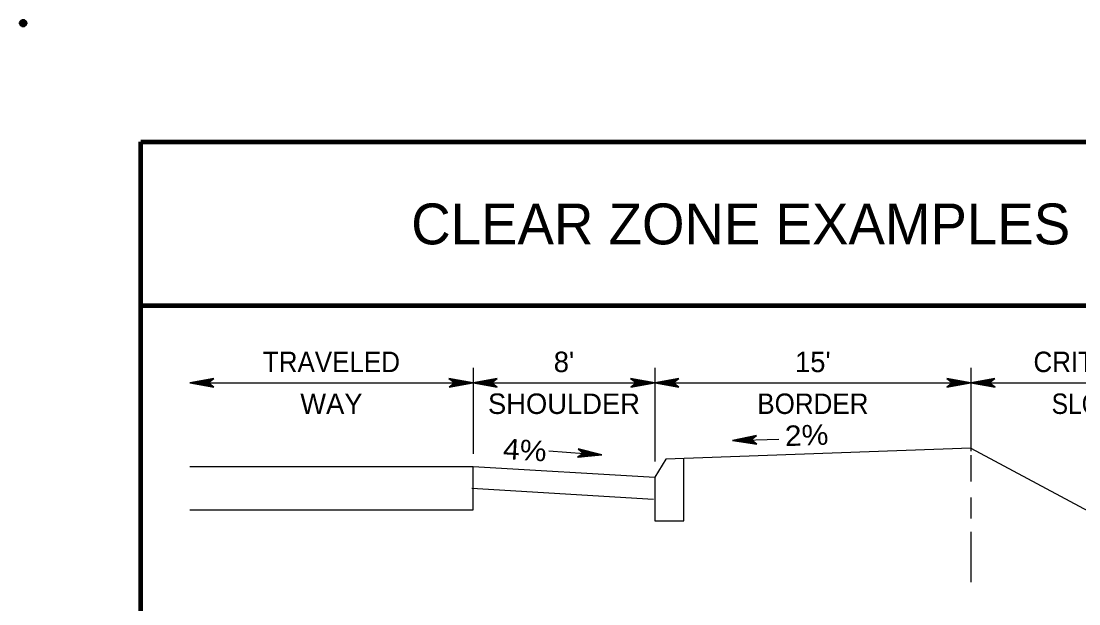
# Model space of a CAD drawing. Extents: x -15.691 to -15.016, y -14.8 to -13.916.
# Drawn here: x -15.6909 to -15.2866, y -14.1387 to -13.9159 of the extents above; entities that cross this region are included whole.
import ezdxf
from ezdxf.enums import TextEntityAlignment as Align

# ---------------------------------------------------------------- set-up
doc = ezdxf.new("R2010")
doc.units = 0
doc.header["$LTSCALE"] = 0.0031
doc.header["$PDMODE"] = 32
doc.header["$PDSIZE"] = 0.00155
for name, color, linetype, lineweight in [('1', 7, 'Continuous', 90), ('24', 7, 'Continuous', 25), ('5', 7, 'Continuous', 25)]:
    doc.layers.add(name, color=color, linetype=linetype, lineweight=lineweight)

msp = doc.modelspace()

# ---------------------------------------------------------------- linework, layer by layer
at = {"layer": '1'}
for p, q in [((-15.645142, -14.753775), (-15.645142, -13.962108)), ((-15.645142, -14.753775), (-15.645142, -13.962108)), ((-15.645142, -14.024608), (-15.061808, -14.024608))]:
    msp.add_line(p, q, dxfattribs=at)
msp.add_lwpolyline([(-15.645142, -13.962108), (-15.186808, -13.962108), (-15.061808, -13.962108)], dxfattribs=at)
msp.add_point((-15.690142, -13.916692), dxfattribs=at)
at = {"layer": '24'}
for p, q in [((-15.518158, -14.048383), (-15.518158, -14.081275)), ((-15.448717, -14.048383), (-15.448717, -14.084308)), ((-15.448717, -14.054167), (-15.327883, -14.054167)), ((-15.327883, -14.054167), (-15.234825, -14.054167)), ((-15.418958, -14.076208), (-15.40125, -14.075708)), ((-15.489158, -14.080208), (-15.468925, -14.081708))]:
    msp.add_line(p, q, dxfattribs=at)
for points in [[(-15.626492, -14.054167), (-15.61725, -14.0558), (-15.619458, -14.054167), (-15.6173, -14.052558), (-15.626492, -14.054167), (-15.625875, -14.05415), (-15.617508, -14.055675), (-15.619633, -14.05415), (-15.617675, -14.052683), (-15.62555, -14.054117), (-15.625242, -14.054167), (-15.618075, -14.055442), (-15.619683, -14.05415), (-15.618025, -14.052892), (-15.6251, -14.054167), (-15.624792, -14.054117), (-15.618525, -14.05525), (-15.619742, -14.054167), (-15.6185, -14.053042), (-15.6239, -14.054117), (-15.623375, -14.054117), (-15.618992, -14.055017), (-15.619842, -14.054192), (-15.618925, -14.053275), (-15.623283, -14.054167), (-15.622792, -14.054192), (-15.619492, -14.054758), (-15.620125, -14.054117), (-15.619442, -14.053483), (-15.622342, -14.054167), (-15.621875, -14.054217), (-15.619892, -14.054592), (-15.620217, -14.05415), (-15.619675, -14.05365), (-15.621633, -14.054167), (-15.620342, -14.054475), (-15.620525, -14.054117), (-15.619958, -14.053767), (-15.621308, -14.054117), (-15.620458, -14.054333), (-15.620817, -14.05405), (-15.620408, -14.053883), (-15.620817, -14.05415), (-15.6206, -14.054192)], [(-15.518158, -14.054167), (-15.5274, -14.052533), (-15.525192, -14.054167), (-15.52735, -14.055775), (-15.518158, -14.054167), (-15.518775, -14.054183), (-15.527142, -14.05265), (-15.525017, -14.054183), (-15.526975, -14.05565), (-15.5191, -14.054208), (-15.519408, -14.054167), (-15.526583, -14.052892), (-15.524975, -14.054183), (-15.526625, -14.055442), (-15.51955, -14.054167), (-15.519858, -14.054208), (-15.526125, -14.053083), (-15.524908, -14.054167), (-15.52615, -14.055292), (-15.52075, -14.054217), (-15.521275, -14.054208), (-15.525658, -14.053317), (-15.524808, -14.054142), (-15.525725, -14.055058), (-15.521367, -14.054167), (-15.521858, -14.054142), (-15.525158, -14.053575), (-15.524525, -14.054217), (-15.525208, -14.054842), (-15.522317, -14.054167), (-15.522775, -14.054117), (-15.524758, -14.053742), (-15.524433, -14.054183), (-15.524975, -14.054683), (-15.523017, -14.054167), (-15.524308, -14.053858), (-15.524125, -14.054208), (-15.524692, -14.054567), (-15.523342, -14.054217), (-15.524192, -14.054), (-15.523833, -14.054283), (-15.524242, -14.05445), (-15.523842, -14.054183), (-15.52405, -14.054142)], [(-15.518158, -14.054167), (-15.508917, -14.0558), (-15.511125, -14.054167), (-15.508967, -14.052558), (-15.518158, -14.054167), (-15.517542, -14.05415), (-15.509175, -14.055675), (-15.5113, -14.05415), (-15.509342, -14.052683), (-15.517217, -14.054117), (-15.516908, -14.054167), (-15.509742, -14.055442), (-15.51135, -14.05415), (-15.509692, -14.052892), (-15.516767, -14.054167), (-15.516458, -14.054117), (-15.510192, -14.05525), (-15.511408, -14.054167), (-15.510167, -14.053042), (-15.515567, -14.054117), (-15.515042, -14.054117), (-15.510658, -14.055017), (-15.511508, -14.054192), (-15.510592, -14.053275), (-15.51495, -14.054167), (-15.514458, -14.054192), (-15.511158, -14.054758), (-15.511792, -14.054117), (-15.511108, -14.053483), (-15.514008, -14.054167), (-15.513542, -14.054217), (-15.511558, -14.054592), (-15.511883, -14.05415), (-15.511342, -14.05365), (-15.5133, -14.054167), (-15.512008, -14.054475), (-15.512192, -14.054117), (-15.511625, -14.053767), (-15.512975, -14.054117), (-15.512125, -14.054333), (-15.512483, -14.05405), (-15.512075, -14.053883), (-15.512475, -14.05415), (-15.512267, -14.054192)], [(-15.448717, -14.054167), (-15.457958, -14.052533), (-15.45575, -14.054167), (-15.457908, -14.055775), (-15.448717, -14.054167), (-15.449325, -14.054183), (-15.457692, -14.05265), (-15.455575, -14.054183), (-15.457533, -14.05565), (-15.449658, -14.054208), (-15.449967, -14.054167), (-15.457133, -14.052892), (-15.455525, -14.054183), (-15.457183, -14.055442), (-15.450108, -14.054167), (-15.450417, -14.054208), (-15.456683, -14.053083), (-15.455458, -14.054167), (-15.456708, -14.055292), (-15.451308, -14.054217), (-15.451825, -14.054208), (-15.456217, -14.053317), (-15.455358, -14.054142), (-15.456283, -14.055058), (-15.451925, -14.054167), (-15.452417, -14.054142), (-15.455717, -14.053575), (-15.455083, -14.054217), (-15.455767, -14.054842), (-15.452867, -14.054167), (-15.453333, -14.054117), (-15.455317, -14.053742), (-15.454992, -14.054183), (-15.455525, -14.054683), (-15.453575, -14.054167), (-15.454867, -14.053858), (-15.454683, -14.054208), (-15.45525, -14.054567), (-15.4539, -14.054217), (-15.45475, -14.054), (-15.454392, -14.054283), (-15.4548, -14.05445), (-15.454392, -14.054183), (-15.454608, -14.054142)], [(-15.448717, -14.054167), (-15.439475, -14.0558), (-15.441683, -14.054167), (-15.439525, -14.052558), (-15.448717, -14.054167), (-15.4481, -14.05415), (-15.439733, -14.055675), (-15.441858, -14.05415), (-15.439892, -14.052683), (-15.447767, -14.054117), (-15.447458, -14.054167), (-15.440292, -14.055442), (-15.4419, -14.05415), (-15.44025, -14.052892), (-15.447325, -14.054167), (-15.447017, -14.054117), (-15.44075, -14.05525), (-15.441967, -14.054167), (-15.440725, -14.053042), (-15.446125, -14.054117), (-15.4456, -14.054117), (-15.441217, -14.055017), (-15.442067, -14.054192), (-15.44115, -14.053275), (-15.445508, -14.054167), (-15.445017, -14.054192), (-15.441717, -14.054758), (-15.44235, -14.054117), (-15.441658, -14.053483), (-15.444558, -14.054167), (-15.444092, -14.054217), (-15.442117, -14.054592), (-15.442442, -14.05415), (-15.4419, -14.05365), (-15.44385, -14.054167), (-15.442558, -14.054475), (-15.44275, -14.054117), (-15.442183, -14.053767), (-15.443525, -14.054117), (-15.442683, -14.054333), (-15.443033, -14.05405), (-15.442625, -14.053883), (-15.443033, -14.05415), (-15.442825, -14.054192)], [(-15.327883, -14.054167), (-15.337125, -14.052533), (-15.334917, -14.054167), (-15.337075, -14.055775), (-15.327883, -14.054167), (-15.328492, -14.054183), (-15.336867, -14.05265), (-15.334742, -14.054183), (-15.3367, -14.05565), (-15.328825, -14.054208), (-15.329133, -14.054167), (-15.3363, -14.052892), (-15.334692, -14.054183), (-15.33635, -14.055442), (-15.329275, -14.054167), (-15.329583, -14.054208), (-15.33585, -14.053083), (-15.334625, -14.054167), (-15.335875, -14.055292), (-15.330475, -14.054217), (-15.330992, -14.054208), (-15.335383, -14.053317), (-15.334533, -14.054142), (-15.33545, -14.055058), (-15.331092, -14.054167), (-15.331583, -14.054142), (-15.334883, -14.053575), (-15.33425, -14.054217), (-15.334933, -14.054842), (-15.332033, -14.054167), (-15.3325, -14.054117), (-15.334483, -14.053742), (-15.334158, -14.054183), (-15.334692, -14.054683), (-15.332742, -14.054167), (-15.334033, -14.053858), (-15.33385, -14.054208), (-15.334417, -14.054567), (-15.333067, -14.054217), (-15.333917, -14.054), (-15.333558, -14.054283), (-15.333967, -14.05445), (-15.333558, -14.054183), (-15.333775, -14.054142)], [(-15.327883, -14.054167), (-15.318642, -14.0558), (-15.32085, -14.054167), (-15.318692, -14.052558), (-15.327883, -14.054167), (-15.327267, -14.05415), (-15.3189, -14.055675), (-15.321025, -14.05415), (-15.319067, -14.052683), (-15.326933, -14.054117), (-15.326625, -14.054167), (-15.319458, -14.055442), (-15.321067, -14.05415), (-15.319417, -14.052892), (-15.326492, -14.054167), (-15.326183, -14.054117), (-15.319917, -14.05525), (-15.321133, -14.054167), (-15.319892, -14.053042), (-15.325292, -14.054117), (-15.324767, -14.054117), (-15.320383, -14.055017), (-15.321233, -14.054192), (-15.320317, -14.053275), (-15.324675, -14.054167), (-15.324183, -14.054192), (-15.320883, -14.054758), (-15.321517, -14.054117), (-15.320833, -14.053483), (-15.323725, -14.054167), (-15.323258, -14.054217), (-15.321283, -14.054592), (-15.321608, -14.05415), (-15.321067, -14.05365), (-15.323025, -14.054167), (-15.321733, -14.054475), (-15.321917, -14.054117), (-15.32135, -14.053767), (-15.3227, -14.054117), (-15.32185, -14.054333), (-15.3222, -14.05405), (-15.3218, -14.053883), (-15.3222, -14.05415), (-15.321992, -14.054192)], [(-15.626492, -14.054167), (-15.518158, -14.054167), (-15.448717, -14.054167)], [(-15.418958, -14.076208), (-15.409675, -14.077583), (-15.411933, -14.076008), (-15.409817, -14.074342), (-15.418958, -14.076208), (-15.41835, -14.076175), (-15.409942, -14.077467), (-15.4121, -14.076), (-15.410192, -14.074483), (-15.418017, -14.076142), (-15.417708, -14.076175), (-15.410508, -14.077242), (-15.41215, -14.076), (-15.410533, -14.0747), (-15.417567, -14.076175), (-15.417267, -14.076117), (-15.410967, -14.077067), (-15.412217, -14.076017), (-15.411008, -14.074858), (-15.416367, -14.076092), (-15.41585, -14.076075), (-15.411442, -14.07685), (-15.412317, -14.07605), (-15.411425, -14.0751), (-15.415758, -14.076117), (-15.415258, -14.076133), (-15.41195, -14.076608), (-15.4126, -14.075983), (-15.411933, -14.075333), (-15.414808, -14.076092), (-15.414342, -14.076125), (-15.41235, -14.07645), (-15.412692, -14.076017), (-15.412167, -14.0755), (-15.4141, -14.076075), (-15.4128, -14.076342), (-15.413, -14.075992), (-15.412442, -14.075625), (-15.413775, -14.076017), (-15.412925, -14.076208), (-15.413292, -14.075933), (-15.412883, -14.075758), (-15.413283, -14.076033), (-15.413067, -14.076067)], [(-15.468925, -14.081708), (-15.478017, -14.079392), (-15.475942, -14.081183), (-15.478208, -14.082625), (-15.468925, -14.081708), (-15.469542, -14.081675), (-15.477767, -14.079533), (-15.475767, -14.081217), (-15.477833, -14.082533), (-15.469875, -14.081683), (-15.470175, -14.081608), (-15.477225, -14.079808), (-15.475717, -14.081217), (-15.477458, -14.08235), (-15.470317, -14.0816), (-15.470625, -14.081625), (-15.476792, -14.080033), (-15.47565, -14.081208), (-15.476975, -14.082242), (-15.471517, -14.081558), (-15.472033, -14.081517), (-15.476342, -14.0803), (-15.47555, -14.081183), (-15.476533, -14.082033), (-15.472125, -14.081467), (-15.472617, -14.0814), (-15.475858, -14.080592), (-15.475275, -14.081283), (-15.476008, -14.081858), (-15.473067, -14.0814), (-15.473525, -14.081317), (-15.475475, -14.080792), (-15.475183, -14.081258), (-15.475758, -14.081717), (-15.473775, -14.081342), (-15.475042, -14.080942), (-15.474875, -14.081308), (-15.475467, -14.081625), (-15.4741, -14.081367), (-15.474933, -14.081092), (-15.4746, -14.0814), (-15.475017, -14.081533), (-15.474592, -14.081308), (-15.4748, -14.081242)]]:
    msp.add_lwpolyline(points, dxfattribs=at)
at = {"layer": '5'}
for p, q in [((-15.327883, -14.048383), (-15.327883, -14.080258)), ((-15.327883, -14.079167), (-15.44455, -14.083333)), ((-15.327883, -14.079167), (-15.234825, -14.129167)), ((-15.44455, -14.083333), (-15.448717, -14.090275)), ((-15.327883, -14.081775), (-15.327883, -14.0919)), ((-15.518158, -14.102775), (-15.518158, -14.086108)), ((-15.518658, -14.094425), (-15.449217, -14.098592)), ((-15.327883, -14.097967), (-15.327883, -14.106058)), ((-15.626492, -14.102775), (-15.518158, -14.102775)), ((-15.327883, -14.111125), (-15.327883, -14.13035))]:
    msp.add_line(p, q, dxfattribs=at)
for points in [[(-15.448717, -14.090275), (-15.448717, -14.106942), (-15.4376, -14.106942), (-15.4376, -14.083333)], [(-15.626492, -14.086108), (-15.518158, -14.086108), (-15.448717, -14.090275)]]:
    msp.add_lwpolyline(points, dxfattribs=at)

# ---------------------------------------------------------------- texts
at = {"layer": '1'}
for s, height, p in [('CLEAR ZONE EXAMPLES', 0.01562, (-15.415883, -14.00125)), ("8'", 0.007817, (-15.483433, -14.050075)), ("15'", 0.007817, (-15.388304, -14.050075)), ('WAY', 0.007817, (-15.572321, -14.066075)), ('SHOULDER', 0.007817, (-15.483438, -14.066075))]:
    msp.add_text(s, height=height, dxfattribs=at).set_placement(p, align=Align.CENTER)
for s, width, p in [('TRAVELED', 0.95, (-15.572321, -14.050075)), ('CRITICAL', 0.95, (-15.28135, -14.050075)), ('BORDER', 0.95, (-15.388296, -14.066075)), ('SLOPE', 0.9, (-15.28135, -14.066075))]:
    msp.add_text(s, height=0.007817, dxfattribs=dict(at, width=width)).set_placement(p, align=Align.CENTER)
at = {"layer": '1', "width": 1.1}
for s, rotation, p in [('2%', 2.045, (-15.390552, -14.078102)), ('4%', 356.566, (-15.498617, -14.083744))]:
    msp.add_text(s, height=0.007817, rotation=rotation, dxfattribs=at).set_placement(p, align=Align.CENTER)

doc.saveas('drawing.dxf')
